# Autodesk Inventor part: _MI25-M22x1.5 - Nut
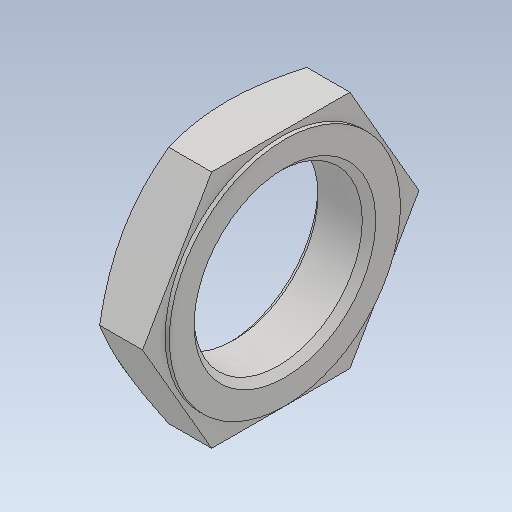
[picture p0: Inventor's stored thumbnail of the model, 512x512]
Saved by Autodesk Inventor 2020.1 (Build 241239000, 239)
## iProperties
Created: 2020-04
Part Number: _MI25-M22x1.5 - Nut
Material: Generic
Document SubType Name: Modeling
Designer: Safarabadi
Density: 1 g/cm^3
Appearance: Default
Author: Safarabadi
Revision Number: NONE
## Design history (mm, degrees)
feature "_MI25-M22x1.5 - Nut"
body "Solid1"
